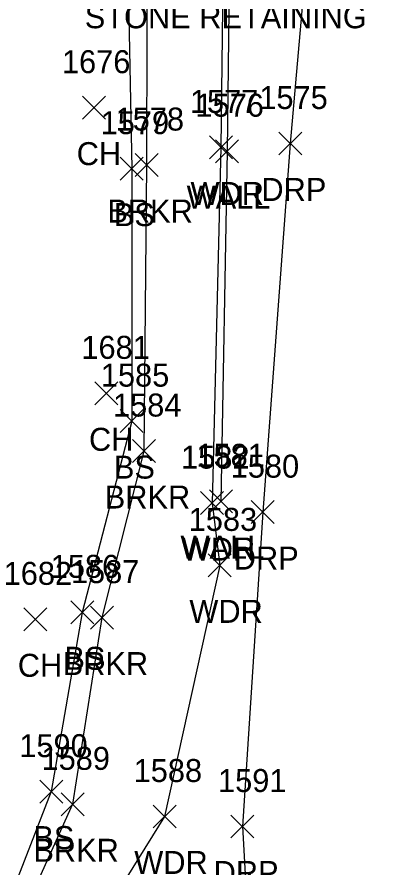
# Model space of a CAD drawing. Extents: x 1651305 to 1654558, y 539481 to 548441.
# Drawn here: x 1654363.9 to 1654395.2, y 544674.1 to 544748.1 of the extents above; entities that cross this region are included whole.
import ezdxf

# ---------------------------------------------------------------- set-up
doc = ezdxf.new("R2010")
doc.units = 0
for name, color, linetype in [('L_A', 7, 'Continuous'), ('L_C', 7, 'Continuous'), ('L_I', 7, 'Continuous'), ('L_TIC', 7, 'Continuous'), ('LAWA', 7, 'Continuous'), ('LAWE', 7, 'Continuous'), ('LELB', 7, 'Continuous'), ('LW', 7, 'Continuous'), ('R_A', 7, 'Continuous'), ('R_I', 7, 'Continuous'), ('R_TIC', 7, 'Continuous'), ('RDP', 7, 'Continuous')]:
    doc.layers.add(name, color=color, linetype=linetype)

msp = doc.modelspace()

# ---------------------------------------------------------------- linework, layer by layer
at = {"layer": 'L_TIC'}
for points in [[(1654369.641, 544739.177), (1654371.641, 544741.177)], [(1654371.641, 544739.177), (1654369.641, 544741.177)], [(1654380.663, 544735.714), (1654382.663, 544737.714)], [(1654382.663, 544735.714), (1654380.663, 544737.714)], [(1654381.201, 544735.391), (1654383.201, 544737.391)], [(1654383.201, 544735.391), (1654381.201, 544737.391)], [(1654374.205, 544734.185), (1654376.205, 544736.185)], [(1654376.205, 544734.185), (1654374.205, 544736.185)], [(1654372.912, 544733.871), (1654374.912, 544735.871)], [(1654374.912, 544733.871), (1654372.912, 544735.871)], [(1654370.71, 544714.324), (1654372.71, 544716.324)], [(1654372.71, 544714.324), (1654370.71, 544716.324)], [(1654372.922, 544711.905), (1654374.922, 544713.905)], [(1654374.922, 544711.905), (1654372.922, 544713.905)], [(1654373.977, 544709.304), (1654375.977, 544711.304)], [(1654375.977, 544709.304), (1654373.977, 544711.304)], [(1654379.899, 544704.776), (1654381.899, 544706.776)], [(1654381.899, 544704.776), (1654379.899, 544706.776)], [(1654380.662, 544704.931), (1654382.662, 544706.931)], [(1654382.662, 544704.931), (1654380.662, 544706.931)], [(1654380.561, 544699.356), (1654382.561, 544701.356)], [(1654382.561, 544699.356), (1654380.561, 544701.356)], [(1654368.617, 544695.27), (1654370.617, 544697.27)], [(1654370.617, 544695.27), (1654368.617, 544697.27)], [(1654364.52, 544694.662), (1654366.52, 544696.662)], [(1654366.52, 544694.662), (1654364.52, 544696.662)], [(1654370.319, 544694.811), (1654372.319, 544696.811)], [(1654372.319, 544694.811), (1654370.319, 544696.811)], [(1654365.919, 544679.671), (1654367.919, 544681.671)], [(1654367.919, 544679.671), (1654365.919, 544681.671)], [(1654367.773, 544678.567), (1654369.773, 544680.567)], [(1654369.773, 544678.567), (1654367.773, 544680.567)], [(1654375.773, 544677.508), (1654377.773, 544679.508)], [(1654377.773, 544677.508), (1654375.773, 544679.508)]]:
    msp.add_lwpolyline(points, dxfattribs=at)
at = {"layer": 'LAWA'}
msp.add_lwpolyline([(1654379.782, 544856.85), (1654381.229, 544808.018), (1654382.76, 544783.063), (1654377.997, 544758.08), (1654381.891, 544756.134), (1654381.663, 544736.714), (1654380.899, 544705.776), (1654381.561, 544700.356), (1654376.773, 544678.508), (1654368.514, 544665.191)], dxfattribs=at)
at = {"layer": 'LAWE'}
msp.add_lwpolyline([(1654375.942, 544856.312), (1654377.084, 544805.548), (1654378.901, 544780.845), (1654375.25, 544758.971), (1654375.205, 544735.185), (1654374.977, 544710.304), (1654371.319, 544695.811), (1654368.773, 544679.567), (1654363.102, 544667.03), (1654358.045, 544658.626), (1654352.364, 544650.107), (1654344.898, 544634.32), (1654334.876, 544605.424), (1654326.397, 544588.829), (1654321.275, 544565.187), (1654313.301, 544530.304), (1654300.219, 544501.736), (1654283.171, 544465.466), (1654261.064, 544441.258)], dxfattribs=at)
at = {"layer": 'LELB'}
msp.add_lwpolyline([(1654374.336, 544855.823), (1654375.217, 544803.448), (1654375.073, 544780.813), (1654373.472, 544758.468), (1654373.912, 544734.871), (1654373.922, 544712.905), (1654369.617, 544696.27), (1654366.919, 544680.671), (1654362.172, 544668.564), (1654357.638, 544659.428), (1654350.702, 544650.566), (1654343.252, 544636.932), (1654333.619, 544607.274), (1654325.309, 544589.171), (1654319.064, 544565.656), (1654310.743, 544531.111), (1654298.268, 544501.75), (1654282.289, 544466.342), (1654260.011, 544442.906)], dxfattribs=at)
at = {"layer": 'LW'}
msp.add_lwpolyline([(1654382.436, 544756.085), (1654382.201, 544736.391), (1654381.662, 544705.931)], dxfattribs=at)
at = {"layer": 'R_TIC'}
for points in [[(1654386.7, 544736.059), (1654388.7, 544738.059)], [(1654388.7, 544736.059), (1654386.7, 544738.059)], [(1654384.299, 544703.988), (1654386.299, 544705.988)], [(1654386.299, 544703.988), (1654384.299, 544705.988)], [(1654382.543, 544676.638), (1654384.543, 544678.638)], [(1654384.543, 544676.638), (1654382.543, 544678.638)]]:
    msp.add_lwpolyline(points, dxfattribs=at)
at = {"layer": 'RDP'}
msp.add_lwpolyline([(1654389.401, 544756.56), (1654387.7, 544737.059), (1654385.299, 544704.988), (1654383.543, 544677.638), (1654384.483, 544660.968), (1654386.242, 544638.223), (1654391.022, 544611.182), (1654397.72, 544578.233), (1654402.202, 544552.331), (1654401.972, 544539.048), (1654399.157, 544531.466), (1654397.052, 544530.18)], dxfattribs=at)

# ---------------------------------------------------------------- texts
at = {"layer": 'L_A'}
for s, p in [('CH', (1654369.129, 544735.177)), ('WALL', (1654378.689, 544731.391)), ('WDR', (1654379.025, 544731.714)), ('BRKR', (1654371.795, 544730.185)), ('BS', (1654372.353, 544729.871)), ('CH', (1654370.198, 544710.324)), ('BS', (1654372.363, 544707.905)), ('BRKR', (1654371.567, 544705.304)), ('WALL', (1654378.15, 544700.931)), ('WDR', (1654378.261, 544700.776)), ('WDR', (1654378.923, 544695.356)), ('BS', (1654368.058, 544691.27)), ('CH', (1654364.008, 544690.662)), ('BRKR', (1654367.91, 544690.811)), ('BS', (1654365.36, 544675.671)), ('BRKR', (1654365.363, 544674.567)), ('WDR', (1654374.135, 544673.508))]:
    msp.add_text(s, height=2, dxfattribs=at).set_placement(p)
at = {"layer": 'L_C'}
msp.add_text('STONE RETAINING', height=2, dxfattribs=at).set_placement((1654369.83, 544747.085))
at = {"layer": 'L_I'}
for s, p in [('1676', (1654367.846, 544743.177)), ('1577', (1654378.97, 544739.714)), ('1576', (1654379.453, 544739.391)), ('1579', (1654371.212, 544737.871)), ('1578', (1654372.512, 544738.185)), ('1681', (1654369.537, 544718.324)), ('1585', (1654371.229, 544715.905)), ('1584', (1654372.284, 544713.304)), ('1582', (1654378.206, 544708.776)), ('1581', (1654379.536, 544708.931)), ('1583', (1654378.868, 544703.356)), ('1682', (1654362.78, 544698.662)), ('1586', (1654366.87, 544699.27)), ('1587', (1654368.627, 544698.811)), ('1590', (1654364.14, 544683.671)), ('1589', (1654366.072, 544682.567)), ('1588', (1654374.08, 544681.508))]:
    msp.add_text(s, height=2, dxfattribs=at).set_placement(p)
at = {"layer": 'R_A'}
for p in [(1654385.188, 544732.059), (1654382.787, 544699.988), (1654381.032, 544672.638)]:
    msp.add_text('DRP', height=2, dxfattribs=at).set_placement(p)
at = {"layer": 'R_I'}
for s, p in [('1575', (1654385.007, 544740.059)), ('1580', (1654382.52, 544707.988)), ('1591', (1654381.418, 544680.638))]:
    msp.add_text(s, height=2, dxfattribs=at).set_placement(p)

doc.saveas('drawing.dxf')
